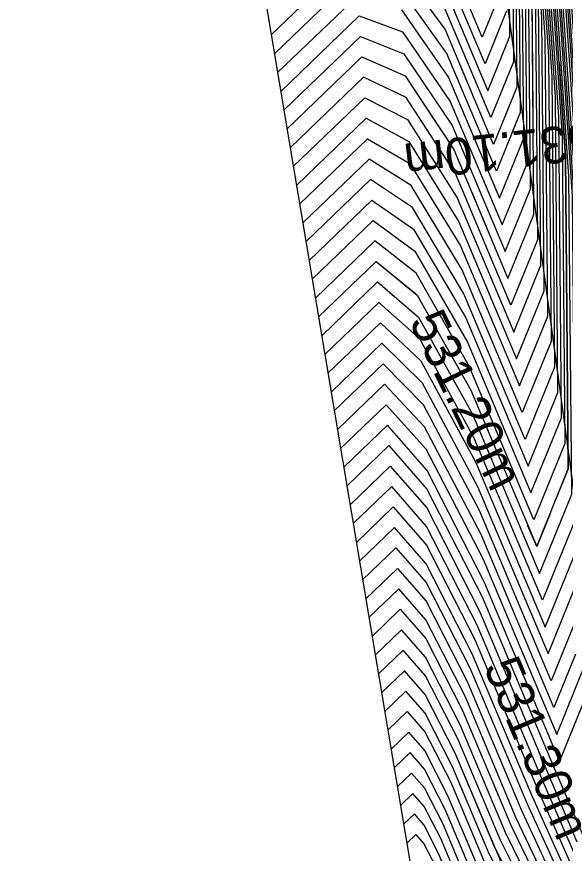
# Model space of a CAD drawing. Extents: x -866683 to -866410, y -1041951 to -1040252.
# Drawn here: x -866470.79 to -866466.31, y -1041914.6 to -1041907.77 of the extents above; entities that cross this region are included whole.
import ezdxf

# ---------------------------------------------------------------- set-up
doc = ezdxf.new("R2010")
doc.units = 0
for name, color, linetype in [('BREAKLINE', 7, 'Continuous'), ('EXTERIOR', 7, 'Continuous'), ('V-VEDL', 7, 'Continuous'), ('V_po_cm', 7, 'Continuous')]:
    doc.layers.add(name, color=color, linetype=linetype)

msp = doc.modelspace()

# ---------------------------------------------------------------- linework, layer by layer
at = {"layer": 'BREAKLINE'}
msp.add_lwpolyline([(-866470.79, -1041895.556), (-866468.781, -1041897.063), (-866467.876, -1041899.685), (-866465.747, -1041915.31), (-866462.994, -1041932.711)], dxfattribs=at)
at = {"layer": 'EXTERIOR'}
msp.add_lwpolyline([(-866470.107, -1041899.606), (-866467.474, -1041915.319), (-866464.952, -1041936.638), (-866464.966, -1041937.083), (-866464.745, -1041941.128), (-866464.731, -1041942.196), (-866464.769, -1041945.786), (-866461.426, -1041946.157), (-866460.329, -1041945.918), (-866459.426, -1041945.724), (-866458.763, -1041945.697), (-866451.679, -1041950.508), (-866451.576, -1041945.087), (-866450.598, -1041944.936), (-866430.202, -1041927.282), (-866428.169, -1041926.387), (-866426.565, -1041925.108), (-866423.347, -1041921.351), (-866422.644, -1041920.368), (-866422.16, -1041919.445), (-866422.107, -1041897.411)], dxfattribs=at)
at = {"layer": 'V-VEDL'}
for points in [[(-866468.3277, -1041910.2246), (-866467.8575, -1041909.7718), (-866467.5217, -1041910.0467), (-866467.0851, -1041910.8229), (-866466.5476, -1041912.1005), (-866466.2902, -1041911.4648), (-866466.3127, -1041908.916), (-866466.6152, -1041904.4541), (-866466.844, -1041901.3152), (-866466.9991, -1041899.4995), (-866467.0805, -1041899.0069), (-866467.1682, -1041898.5759), (-866467.2622, -1041898.2067), (-866467.3624, -1041897.8993), (-866467.5074, -1041897.4756), (-866467.6972, -1041896.9359), (-866468.1665, -1041895.624)], [(-866468.5848, -1041908.6901), (-866467.973, -1041908.1009), (-866467.6216, -1041908.2553), (-866467.2246, -1041908.8586), (-866466.7819, -1041909.9108), (-866466.5699, -1041909.3873), (-866466.5884, -1041907.288), (-866466.8376, -1041903.613), (-866467.026, -1041901.0277), (-866467.1538, -1041899.5322), (-866467.2208, -1041899.1265), (-866467.3096, -1041898.7206), (-866467.4202, -1041898.3147), (-866467.5526, -1041897.9086), (-866467.7059, -1041897.4562), (-866467.88, -1041896.9573), (-866468.2701, -1041895.8667)], [(-866468.0705, -1041911.759), (-866467.742, -1041911.4426), (-866467.4443, -1041911.7845), (-866467.0132, -1041912.6265), (-866465.8841, -1041915.3107)], [(-866466.5694, -1041915.3143), (-866467.2118, -1041913.7871), (-866467.4571, -1041913.308), (-866467.6265, -1041913.1135), (-866467.8134, -1041913.2935)]]:
    msp.add_lwpolyline(points, dxfattribs=at)
at = {"layer": 'V_po_cm'}
for points in [[(-866468.5077, -1041909.1504), (-866467.9384, -1041908.6022), (-866467.5916, -1041908.7927), (-866467.1827, -1041909.4479), (-866466.7116, -1041910.5677), (-866466.486, -1041910.0105), (-866466.5057, -1041907.7764), (-866466.7709, -1041903.8653)], [(-866468.4819, -1041909.3039), (-866467.9268, -1041908.7693), (-866467.5816, -1041908.9718), (-866467.1688, -1041909.6443), (-866466.6882, -1041910.7867), (-866466.458, -1041910.2183), (-866466.4782, -1041907.9392), (-866466.7486, -1041903.9494)], [(-866466.381, -1041904.0065), (-866466.1148, -1041907.9343), (-866465.9097, -1041910.9374), (-866465.7659, -1041913.016), (-866465.6834, -1041914.17), (-866465.6249, -1041915.0054), (-866465.5904, -1041915.5221), (-866465.58, -1041915.7203), (-866465.5647, -1041915.9626), (-866465.5444, -1041916.249), (-866465.5191, -1041916.5795), (-866465.5245, -1041916.6911), (-866465.5604, -1041916.5838), (-866465.6269, -1041916.2574), (-866465.7381, -1041915.9712), (-866465.894, -1041915.725), (-866466.0947, -1041915.5189), (-866466.3679, -1041915.0499), (-866466.7138, -1041914.3179), (-866467.1324, -1041913.3228), (-866467.452, -1041912.6986), (-866467.6727, -1041912.4451), (-866467.9163, -1041912.6797)], [(-866466.7264, -1041904.0335), (-866466.4506, -1041908.102), (-866466.4301, -1041910.426), (-866466.6648, -1041911.0056), (-866467.1548, -1041909.8407), (-866467.5716, -1041909.151), (-866467.9153, -1041908.9363), (-866468.4562, -1041909.4573)], [(-866466.7042, -1041904.1176), (-866466.423, -1041908.2648), (-866466.4021, -1041910.6338), (-866466.6414, -1041911.2246), (-866467.1409, -1041910.0372), (-866467.5616, -1041909.3301), (-866467.9037, -1041909.1034), (-866468.4305, -1041909.6108)], [(-866467.942, -1041912.5263), (-866467.6842, -1041912.278), (-866467.4507, -1041912.5463), (-866467.1125, -1041913.2068), (-866466.6696, -1041914.2596), (-866466.3158, -1041915.0217), (-866466.0512, -1041915.4928), (-866465.8757, -1041915.6732), (-866465.7392, -1041915.8885), (-866465.6419, -1041916.139), (-866465.5837, -1041916.4245), (-866465.5523, -1041916.5185), (-866465.5476, -1041916.4208), (-866465.5697, -1041916.1316), (-866465.5875, -1041915.881), (-866465.6009, -1041915.669), (-866465.61, -1041915.4956), (-866465.6401, -1041915.0435), (-866465.6913, -1041914.3125), (-866465.7636, -1041913.3028), (-866465.9038, -1041911.2718), (-866466.1119, -1041908.2198), (-866466.3881, -1041904.1466)], [(-866468.4048, -1041909.7642), (-866467.8922, -1041909.2705), (-866467.5517, -1041909.5093), (-866467.1269, -1041910.2336), (-866466.6179, -1041911.4436), (-866466.3741, -1041910.8416), (-866466.3955, -1041908.4276), (-866466.6819, -1041904.2017)], [(-866468.3791, -1041909.9177), (-866467.8806, -1041909.4376), (-866467.5417, -1041909.6884), (-866467.113, -1041910.43), (-866466.5945, -1041911.6625), (-866466.3461, -1041911.0493), (-866466.3679, -1041908.5904), (-866466.6597, -1041904.2858)], [(-866467.9677, -1041912.3728), (-866467.6958, -1041912.111), (-866467.4494, -1041912.3939), (-866467.0926, -1041913.0907), (-866466.6254, -1041914.2014), (-866466.2638, -1041914.9934), (-866466.0077, -1041915.4667), (-866465.8573, -1041915.6213), (-866465.7404, -1041915.8059), (-866465.6569, -1041916.0206), (-866465.607, -1041916.2653), (-866465.5801, -1041916.3458), (-866465.5761, -1041916.2621), (-866465.5951, -1041916.0142), (-866465.6103, -1041915.7994), (-866465.6218, -1041915.6177), (-866465.6296, -1041915.4691), (-866465.6554, -1041915.0815), (-866465.6993, -1041914.455), (-866465.7612, -1041913.5895), (-866465.8978, -1041911.6063), (-866466.1091, -1041908.5053), (-866466.3951, -1041904.2866)], [(-866466.6375, -1041904.37), (-866466.3403, -1041908.7532), (-866466.3182, -1041911.2571), (-866466.5711, -1041911.8815), (-866467.099, -1041910.6265), (-866467.5317, -1041909.8675), (-866467.8691, -1041909.6047), (-866468.3534, -1041910.0711)], [(-866466.4022, -1041904.4267), (-866466.1063, -1041908.7908), (-866465.8918, -1041911.9407), (-866465.7588, -1041913.8763), (-866465.7072, -1041914.5975), (-866465.6707, -1041915.1196), (-866465.6491, -1041915.4426), (-866465.6427, -1041915.5664), (-866465.6331, -1041915.7178), (-866465.6204, -1041915.8969), (-866465.6046, -1041916.1035), (-866465.6079, -1041916.1732), (-866465.6304, -1041916.1061), (-866465.6719, -1041915.9022), (-866465.7415, -1041915.7232), (-866465.8389, -1041915.5694), (-866465.9643, -1041915.4406), (-866466.2117, -1041914.9652), (-866466.5812, -1041914.1432), (-866467.0728, -1041912.9747), (-866467.4481, -1041912.2416), (-866467.7074, -1041911.9439), (-866467.9934, -1041912.2194)], [(-866468.302, -1041910.378), (-866467.846, -1041909.9389), (-866467.5117, -1041910.2258), (-866467.0711, -1041911.0194), (-866466.5242, -1041912.3194), (-866466.2622, -1041911.6726), (-866466.2852, -1041909.0788), (-866466.593, -1041904.5382)], [(-866468.0191, -1041912.0659), (-866467.7189, -1041911.7768), (-866467.4469, -1041912.0892), (-866467.0529, -1041912.8586), (-866466.537, -1041914.085), (-866466.1597, -1041914.937), (-866465.9208, -1041915.4145), (-866465.8205, -1041915.5175), (-866465.7426, -1041915.6406), (-866465.687, -1041915.7837), (-866465.6537, -1041915.9469), (-866465.6357, -1041916.0006), (-866465.6331, -1041915.9448), (-866465.6457, -1041915.7795), (-866465.6559, -1041915.6363), (-866465.6635, -1041915.5151), (-866465.6687, -1041915.4161), (-866465.6859, -1041915.1577), (-866465.7152, -1041914.74), (-866465.7565, -1041914.163), (-866465.8859, -1041912.2751), (-866466.1035, -1041909.0764), (-866466.4092, -1041904.5667)], [(-866466.5708, -1041904.6223), (-866466.2576, -1041909.2416), (-866466.2343, -1041911.8804), (-866466.5008, -1041912.5384), (-866467.0572, -1041911.2158), (-866467.5017, -1041910.405), (-866467.8344, -1041910.1059), (-866468.2762, -1041910.5314)], [(-866468.2505, -1041910.6849), (-866467.8229, -1041910.273), (-866467.4917, -1041910.5841), (-866467.0432, -1041911.4122), (-866466.4774, -1041912.7574), (-866466.2063, -1041912.0881), (-866466.23, -1041909.4045), (-866466.5485, -1041904.7064)], [(-866466.4162, -1041904.7068), (-866466.1006, -1041909.3619), (-866465.8799, -1041912.6095), (-866465.7541, -1041914.4498), (-866465.7231, -1041914.8825), (-866465.7012, -1041915.1958), (-866465.6883, -1041915.3896), (-866465.6844, -1041915.4639), (-866465.6786, -1041915.5547), (-866465.671, -1041915.6621), (-866465.6615, -1041915.7861), (-866465.6635, -1041915.8279), (-866465.677, -1041915.7877), (-866465.702, -1041915.6653), (-866465.7437, -1041915.5579), (-866465.8021, -1041915.4656), (-866465.8774, -1041915.3884), (-866466.1076, -1041914.9087), (-866466.4928, -1041914.0268), (-866467.033, -1041912.7426), (-866467.4456, -1041911.9369), (-866467.7305, -1041911.6097), (-866468.0448, -1041911.9125)], [(-866466.5774, -1041908.5391), (-866466.5884, -1041907.288), (-866466.7669, -1041904.6552)], [(-866468.2248, -1041910.8383), (-866467.8113, -1041910.4401), (-866467.4817, -1041910.7633), (-866467.0293, -1041911.6087), (-866466.4539, -1041912.9763), (-866466.1783, -1041912.2959), (-866466.2025, -1041909.5673), (-866466.5263, -1041904.7905)], [(-866466.5041, -1041904.8746), (-866466.1749, -1041909.7301), (-866466.1504, -1041912.5036), (-866466.4305, -1041913.1953), (-866467.0153, -1041911.8051), (-866467.4717, -1041910.9424), (-866467.7998, -1041910.6072), (-866468.1991, -1041910.9918)], [(-866466.4818, -1041904.9587), (-866466.1473, -1041909.8929), (-866466.1224, -1041912.7114), (-866466.4071, -1041913.4143), (-866467.0014, -1041912.0015), (-866467.4617, -1041911.1215), (-866467.7882, -1041910.7743), (-866468.1734, -1041911.1452)], [(-866468.0963, -1041911.6056), (-866467.7536, -1041911.2755), (-866467.443, -1041911.6322), (-866466.9933, -1041912.5105), (-866466.4044, -1041913.9104), (-866466.0035, -1041914.8523), (-866465.7905, -1041915.3361), (-866465.7654, -1041915.3619), (-866465.7459, -1041915.3926), (-866465.732, -1041915.4284), (-866465.7237, -1041915.4692), (-866465.7192, -1041915.4826), (-866465.7185, -1041915.4687), (-866465.7217, -1041915.4274), (-866465.7242, -1041915.3916), (-866465.7261, -1041915.3613), (-866465.7274, -1041915.3365), (-866465.7317, -1041915.2719), (-866465.739, -1041915.1675), (-866465.7494, -1041915.0233), (-866465.868, -1041913.2784), (-866466.095, -1041909.9329), (-866466.4303, -1041904.9869)], [(-866468.1477, -1041911.2987), (-866467.7767, -1041910.9414), (-866467.4517, -1041911.3007), (-866466.9874, -1041912.198), (-866466.3837, -1041913.6332), (-866466.0944, -1041912.9191), (-866466.1197, -1041910.0557), (-866466.4596, -1041905.0428)], [(-866466.4373, -1041905.127), (-866466.0922, -1041910.2185), (-866466.0665, -1041913.1269), (-866466.3602, -1041913.8522), (-866466.9735, -1041912.3944), (-866467.4418, -1041911.4798), (-866467.7651, -1041911.1085), (-866468.122, -1041911.4521)], [(-866466.1402, -1041905.3645), (-866465.9633, -1041907.9276), (-866465.7872, -1041910.4353), (-866465.6118, -1041912.8875), (-866465.4875, -1041914.6627), (-866465.4143, -1041915.7608), (-866465.3922, -1041916.1818), (-866465.3596, -1041916.6967), (-866465.3165, -1041917.3053), (-866465.2628, -1041918.0078), (-866465.2741, -1041918.2449), (-866465.3504, -1041918.0168), (-866465.4918, -1041917.3233), (-866465.7282, -1041916.715), (-866466.0595, -1041916.1919), (-866466.4858, -1041915.754), (-866466.8365, -1041915.3039), (-866467.1116, -1041914.8417), (-866467.3111, -1041914.3673), (-866467.4635, -1041914.0697), (-866467.5687, -1041913.9489), (-866467.6848, -1041914.0607)], [(-866466.1374, -1041905.65), (-866465.9574, -1041908.262), (-866465.7848, -1041910.722), (-866465.6197, -1041913.03), (-866465.5027, -1041914.7008), (-866465.4338, -1041915.7343), (-866465.4131, -1041916.1306), (-866465.3824, -1041916.6151), (-866465.3418, -1041917.1879), (-866465.2913, -1041917.8491), (-866465.3019, -1041918.0723), (-866465.3738, -1041917.8575), (-866465.5068, -1041917.2049), (-866465.7293, -1041916.6324), (-866466.0411, -1041916.1401), (-866466.4423, -1041915.7279), (-866466.7844, -1041915.2757), (-866467.0674, -1041914.7835), (-866467.2913, -1041914.2513), (-866467.4622, -1041913.9174), (-866467.5803, -1041913.7818), (-866467.7106, -1041913.9073)], [(-866466.1345, -1041905.9356), (-866465.9514, -1041908.5964), (-866465.7825, -1041911.0088), (-866465.6277, -1041913.1725), (-866465.518, -1041914.7389), (-866465.4534, -1041915.7078), (-866465.434, -1041916.0793), (-866465.4052, -1041916.5335), (-866465.3671, -1041917.0706), (-866465.3197, -1041917.6904), (-866465.3297, -1041917.8996), (-866465.3971, -1041917.6983), (-866465.5218, -1041917.0865), (-866465.7304, -1041916.5497), (-866466.0227, -1041916.0882), (-866466.3988, -1041915.7018), (-866466.7323, -1041915.2475), (-866467.0232, -1041914.7253), (-866467.2714, -1041914.1352), (-866467.4609, -1041913.765), (-866467.5918, -1041913.6147), (-866467.7363, -1041913.7538)], [(-866467.3222, -1041907.4835), (-866466.9459, -1041908.378), (-866466.7657, -1041907.933), (-866466.7814, -1041906.1484)], [(-866467.762, -1041913.6004), (-866467.6034, -1041913.4476), (-866467.4597, -1041913.6127), (-866467.2515, -1041914.0192), (-866466.979, -1041914.6671), (-866466.6803, -1041915.2192), (-866466.3554, -1041915.6757), (-866466.0043, -1041916.0363), (-866465.7315, -1041916.4671), (-866465.5368, -1041916.968), (-866465.4204, -1041917.5391), (-866465.3575, -1041917.727), (-866465.3482, -1041917.5317), (-866465.3925, -1041916.9532), (-866465.428, -1041916.452), (-866465.4548, -1041916.028), (-866465.473, -1041915.6813), (-866465.5333, -1041914.7769), (-866465.6356, -1041913.315), (-866465.7801, -1041911.2955), (-866465.9455, -1041908.9309), (-866466.1317, -1041906.2211)], [(-866466.7539, -1041906.3112), (-866466.7377, -1041908.1407), (-866466.9225, -1041908.597), (-866467.3082, -1041907.6799)], [(-866466.7263, -1041906.474), (-866466.7097, -1041908.3485), (-866466.8991, -1041908.8159), (-866467.2943, -1041907.8764), (-866467.6715, -1041907.3596)], [(-866466.1289, -1041906.5066), (-866465.9395, -1041909.2653), (-866465.7777, -1041911.5823), (-866465.6436, -1041913.4575), (-866465.5485, -1041914.815), (-866465.4926, -1041915.6547), (-866465.4757, -1041915.9767), (-866465.4508, -1041916.3704), (-866465.4178, -1041916.8358), (-866465.3767, -1041917.373), (-866465.3854, -1041917.5543), (-866465.4437, -1041917.3799), (-866465.5519, -1041916.8496), (-866465.7326, -1041916.3844), (-866465.986, -1041915.9844), (-866466.3119, -1041915.6495), (-866466.6282, -1041915.191), (-866466.9348, -1041914.6089), (-866467.2317, -1041913.9031), (-866467.4584, -1041913.4604), (-866467.6149, -1041913.2806), (-866467.7877, -1041913.4469)], [(-866466.6987, -1041906.6368), (-866466.6818, -1041908.5562), (-866466.8756, -1041909.0349), (-866467.2803, -1041908.0728), (-866467.6616, -1041907.5387)], [(-866467.6516, -1041907.7178), (-866467.2664, -1041908.2693), (-866466.8522, -1041909.2539), (-866466.6538, -1041908.764), (-866466.6712, -1041906.7996)], [(-866468.6362, -1041908.3832), (-866467.9962, -1041907.7667), (-866467.6416, -1041907.897), (-866467.2525, -1041908.4657), (-866466.8288, -1041909.4729), (-866466.6258, -1041908.9717), (-866466.6436, -1041906.9624)], [(-866467.6077, -1041914.5211), (-866467.5341, -1041914.4502), (-866467.4673, -1041914.5268), (-866467.3707, -1041914.7155), (-866467.2442, -1041915.0163), (-866466.9926, -1041915.3886), (-866466.6161, -1041915.8324), (-866466.1146, -1041916.3476), (-866465.7248, -1041916.963), (-866465.4468, -1041917.6786), (-866465.2805, -1041918.4944), (-866465.1906, -1041918.7628), (-866465.1773, -1041918.4838), (-866465.2405, -1041917.6574), (-866465.2913, -1041916.9414), (-866465.3296, -1041916.3357), (-866465.3556, -1041915.8404), (-866465.4416, -1041914.5485), (-866465.5879, -1041912.46), (-866465.7943, -1041909.575), (-866465.9812, -1041906.9243)], [(-866466.1232, -1041907.0777), (-866465.9276, -1041909.9341), (-866465.773, -1041912.1558), (-866465.6595, -1041913.7425), (-866465.5791, -1041914.8912), (-866465.5317, -1041915.6017), (-866465.5174, -1041915.8741), (-866465.4964, -1041916.2073), (-866465.4684, -1041916.6011), (-866465.4337, -1041917.0556), (-866465.441, -1041917.2091), (-866465.4904, -1041917.0614), (-866465.5819, -1041916.6127), (-866465.7348, -1041916.2191), (-866465.9492, -1041915.8807), (-866466.225, -1041915.5973), (-866466.5241, -1041915.1346), (-866466.8464, -1041914.4925), (-866467.1919, -1041913.671), (-866467.4558, -1041913.1557), (-866467.638, -1041912.9464), (-866467.8391, -1041913.14)], [(-866466.8216, -1041907.5174), (-866466.9928, -1041907.9401), (-866467.3501, -1041907.0906)], [(-866468.6105, -1041908.5366), (-866467.9846, -1041907.9338), (-866467.6316, -1041908.0761), (-866467.2385, -1041908.6621), (-866466.8054, -1041909.6918), (-866466.5979, -1041909.1795), (-866466.616, -1041907.1252)], [(-866468.0308, -1041907.2655), (-866468.7134, -1041907.9228)], [(-866465.9753, -1041907.2587), (-866465.7919, -1041909.8618), (-866465.5959, -1041912.6025), (-866465.4569, -1041914.5866), (-866465.3751, -1041915.8139), (-866465.3505, -1041916.2844), (-866465.3141, -1041916.8598), (-866465.2658, -1041917.5401), (-866465.2058, -1041918.3251), (-866465.2185, -1041918.5902), (-866465.3038, -1041918.3352), (-866465.4618, -1041917.5602), (-866465.7259, -1041916.8803), (-866466.0962, -1041916.2957), (-866466.5727, -1041915.8062), (-866466.9406, -1041915.3604), (-866467.2, -1041914.9581), (-866467.3509, -1041914.5995), (-866467.4661, -1041914.3744), (-866467.5456, -1041914.2831), (-866467.6334, -1041914.3676)], [(-866466.7936, -1041907.7252), (-866466.9693, -1041908.159), (-866467.3361, -1041907.2871)], [(-866466.1204, -1041907.3632), (-866465.9216, -1041910.2686), (-866465.7707, -1041912.4425), (-866465.6674, -1041913.885), (-866465.5943, -1041914.9292), (-866465.5513, -1041915.5752), (-866465.5383, -1041915.8229), (-866465.5191, -1041916.1257), (-866465.4938, -1041916.4837), (-866465.4622, -1041916.8969), (-866465.4688, -1041917.0364), (-866465.5137, -1041916.9022), (-866465.5969, -1041916.4943), (-866465.7359, -1041916.1365), (-866465.9308, -1041915.8288), (-866466.1816, -1041915.5712), (-866466.472, -1041915.1063), (-866466.8022, -1041914.4343), (-866467.1721, -1041913.555), (-866467.4545, -1041913.0033), (-866467.6496, -1041912.7793), (-866467.8648, -1041912.9866)], [(-866468.0193, -1041907.4326), (-866468.6876, -1041908.0763)], [(-866466.5609, -1041907.4508), (-866466.5419, -1041909.595), (-866466.7585, -1041910.1298), (-866467.2106, -1041909.055), (-866467.6116, -1041908.4344), (-866467.9615, -1041908.268), (-866468.5591, -1041908.8435)], [(-866468.6619, -1041908.2297), (-866468.0077, -1041907.5997)], [(-866468.5334, -1041908.997), (-866467.9499, -1041908.4351), (-866467.6016, -1041908.6136), (-866467.1967, -1041909.2514), (-866466.7351, -1041910.3487), (-866466.514, -1041909.8028), (-866466.5333, -1041907.6136)], [(-866467.8905, -1041912.8332), (-866467.6611, -1041912.6122), (-866467.4533, -1041912.851), (-866467.1522, -1041913.4389), (-866466.758, -1041914.3761), (-866466.42, -1041915.0781), (-866466.1381, -1041915.5451), (-866465.9124, -1041915.7769), (-866465.737, -1041916.0538), (-866465.6119, -1041916.3759), (-866465.5371, -1041916.743), (-866465.4966, -1041916.8638), (-866465.4906, -1041916.7382), (-866465.5191, -1041916.3663), (-866465.5419, -1041916.0441), (-866465.5592, -1041915.7716), (-866465.5709, -1041915.5487), (-866465.6096, -1041914.9673), (-866465.6754, -1041914.0275), (-866465.7683, -1041912.7293), (-866465.9157, -1041910.603), (-866466.1176, -1041907.6487)], [(-866465.9693, -1041907.5932), (-866465.7896, -1041910.1485), (-866465.6038, -1041912.745), (-866465.4722, -1041914.6246), (-866465.3947, -1041915.7873), (-866465.3714, -1041916.2331), (-866465.3368, -1041916.7783), (-866465.2912, -1041917.4227), (-866465.2343, -1041918.1664), (-866465.2463, -1041918.4175), (-866465.3271, -1041918.176), (-866465.4768, -1041917.4417), (-866465.7271, -1041916.7977), (-866466.0779, -1041916.2438), (-866466.5292, -1041915.7801), (-866466.8885, -1041915.3322), (-866467.1558, -1041914.8999), (-866467.331, -1041914.4834), (-866467.4648, -1041914.2221), (-866467.5572, -1041914.116), (-866467.6591, -1041914.2142)], [(-866468.5848, -1041908.6901), (-866467.973, -1041908.1009), (-866467.6216, -1041908.2553), (-866467.3743, -1041908.6311)], [(-866466.365, -1041908.1445), (-866466.3127, -1041908.916), (-866466.2902, -1041911.4648), (-866466.3907, -1041911.7129)], [(-866467.0804, -1041909.2012), (-866466.7819, -1041909.9108), (-866466.5699, -1041909.3873), (-866466.5721, -1041909.1425)], [(-866468.3277, -1041910.2246), (-866467.8575, -1041909.7718), (-866467.5363, -1041910.0347)], [(-866468.0705, -1041911.759), (-866467.742, -1041911.4426), (-866467.4443, -1041911.7845), (-866467.0132, -1041912.6265), (-866466.9183, -1041912.852)], [(-866466.4413, -1041911.8378), (-866466.5476, -1041912.1005), (-866466.6215, -1041911.9249)], [(-866466.243, -1041915.6496), (-866466.2685, -1041915.6234), (-866466.5762, -1041915.1628), (-866466.8906, -1041914.5507), (-866467.2118, -1041913.7871), (-866467.4571, -1041913.308), (-866467.6265, -1041913.1135), (-866467.8134, -1041913.2935)]]:
    msp.add_lwpolyline(points, dxfattribs=at)

# ---------------------------------------------------------------- texts
for s, rotation, p in [('531.10m', 186.58317, (-866466.0927, -1041908.6342)), ('531.20m', 295.80812, (-866467.5919, -1041910.2626)), ('531.30m', 293.02789, (-866466.9836, -1041913.0818))]:
    msp.add_text(s, height=0.3, rotation=rotation, dxfattribs=at).set_placement(p)

doc.saveas('drawing.dxf')
